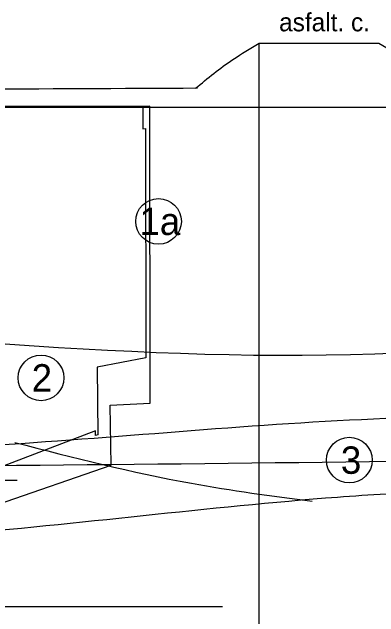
# Model space of a CAD drawing. Extents: x 3042 to 4120, y 576 to 2694.
# Drawn here: x 3274.8 to 3294.89, y 1141.84 to 1174.99 of the extents above; entities that cross this region are included whole.
import ezdxf

# ---------------------------------------------------------------- set-up
doc = ezdxf.new("R2010")
doc.units = 0
for name, color, linetype in [('61', 7, 'Continuous'), ('HPV', 7, 'Continuous'), ('komunikace', 7, 'Continuous'), ('nádrže', 7, 'Continuous'), ('pomocna', 7, 'Continuous'), ('rozhraní', 7, 'Continuous')]:
    doc.layers.add(name, color=color, linetype=linetype)

msp = doc.modelspace()

# ---------------------------------------------------------------- linework, layer by layer
at = {"layer": '61'}
msp.add_line((3270.077, 1149.329), (3275.072, 1149.329), dxfattribs=at)
at = {"layer": 'HPV'}
msp.add_spline([(3244.526, 1150.071), (3259.592, 1150.071), (3342.022, 1151.082), (3387.314, 1151.702), (3432.605, 1152.427), (3477.894, 1153.253), (3523.182, 1154.177), (3531.662, 1154.202)], degree=3, dxfattribs=at)
at = {"layer": 'komunikace'}
msp.add_line((3288.332, 1173.279), (3294.892, 1173.279), dxfattribs=at)
at = {"layer": 'nádrže'}
msp.add_line((3261.732, 1169.829), (3282.352, 1169.829), dxfattribs=at)
msp.add_lwpolyline([(3273.973, 1148.004), (3280.224, 1150.16), (3280.179, 1153.445), (3282.37, 1153.558), (3282.352, 1169.829), (3281.952, 1169.818), (3281.953, 1168.596), (3282.107, 1168.6), (3282.121, 1156.048), (3279.465, 1155.532), (3279.494, 1151.814), (3279.363, 1151.789), (3279.361, 1152.046), (3272.91, 1149.581)], dxfattribs=at)
at = {"layer": 'pomocna'}
for p, q in [((3288.332, 1114.779), (3288.332, 1173.279)), ((3288.332, 1173.279), (3294.892, 1173.279)), ((3196.316, 1169.779), (3297.868, 1169.779))]:
    msp.add_line(p, q, dxfattribs=at)
at = {"layer": 'rozhraní'}
msp.add_line((3286.32, 1142.401), (3240.614, 1142.401), dxfattribs=at)
for centre in [(3282.82, 1163.519), (3276.383, 1154.942), (3293.272, 1150.434)]:
    msp.add_circle(centre, 1.25, dxfattribs=at)
for points in [[(3284.844, 1170.812), (3286.895, 1172.39), (3288.332, 1173.279)], [(3294.892, 1173.279), (3296.558, 1172.232), (3297.071, 1171.838)], [(3205.836, 1171.092), (3218.112, 1171.316), (3259.655, 1170.829), (3284.962, 1170.829)], [(3207.004, 1158.78), (3218.112, 1158.879), (3259.973, 1157.829), (3302.602, 1156.829), (3342.022, 1163.729), (3364.19, 1163.729)], [(3245.619, 1151.047), (3259.973, 1150.829), (3265.305, 1150.858), (3270.634, 1151.067), (3281.288, 1151.798), (3291.941, 1152.562), (3302.602, 1152.896), (3312.456, 1152.774), (3322.31, 1152.547), (3332.166, 1152.327), (3342.022, 1152.229), (3376.196, 1152.229)], [(3274.956, 1151.401), (3284.621, 1149.163), (3291.244, 1148.178)], [(3244.874, 1145.836), (3259.987, 1145.829), (3265.324, 1145.957), (3270.658, 1146.296), (3281.314, 1147.328), (3291.961, 1148.361), (3297.282, 1148.701), (3299.942, 1148.796), (3302.602, 1148.829), (3307.542, 1148.609), (3312.466, 1148.031), (3322.293, 1146.278), (3332.129, 1144.526), (3337.065, 1143.948), (3342.022, 1143.729), (3376.542, 1143.729)]]:
    msp.add_spline(points, degree=3, dxfattribs=at)

# ---------------------------------------------------------------- texts
at = {"layer": 'komunikace'}
msp.add_text('asfalt. c.', height=1, dxfattribs=at).set_placement((3289.425, 1173.934))
at = {"layer": 'rozhraní'}
for s, p in [('1a', (3281.777, 1162.769)), ('2', (3275.875, 1154.192)), ('3', (3292.81, 1149.684))]:
    msp.add_text(s, height=1.5, dxfattribs=at).set_placement(p)

doc.saveas('drawing.dxf')
